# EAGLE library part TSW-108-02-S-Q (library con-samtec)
THROUGH-HOLE .025" SQ POST HEADER Source: Samtec TSW.pdf
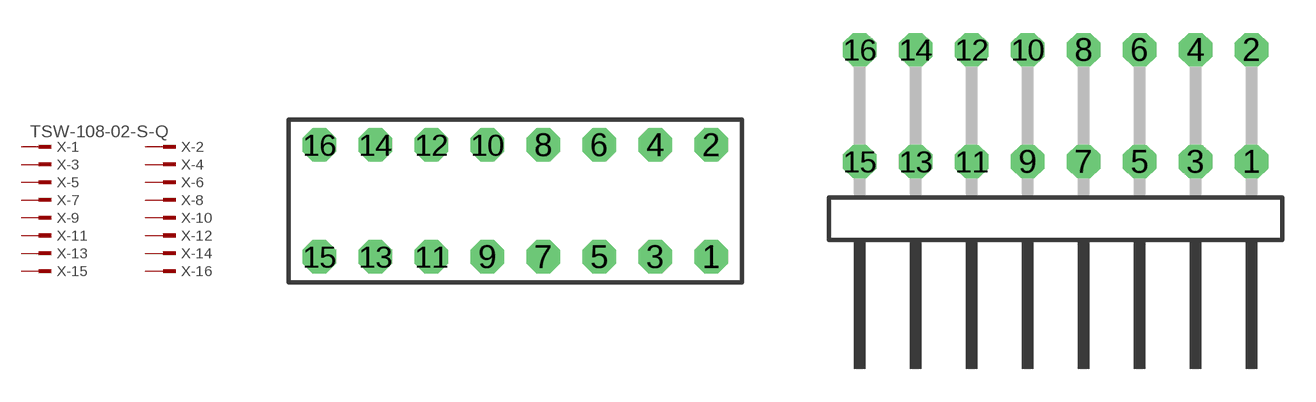
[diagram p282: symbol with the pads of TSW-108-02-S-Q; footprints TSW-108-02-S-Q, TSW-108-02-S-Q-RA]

Designator prefix X; gates -1=MPINV -2=MPIN -3=MPIN -4=MPIN -5=MPIN -6=MPIN -7=MPIN -8=MPIN -9=MPIN -10=MPIN -11=MPIN -12=MPIN -13=MPIN -14=MPIN -15=MPIN -16=MPIN

## TSW-108-02-S-Q (OC_FARNELL: unknown; OC_NEWARK: unknown)  [TSW-108-02-S-Q]
1  -1:1  pas
2  -2:1  pas
3  -3:1  pas
4  -4:1  pas
5  -5:1  pas
6  -6:1  pas
7  -7:1  pas
8  -8:1  pas
9  -9:1  pas
10  -10:1  pas
11  -11:1  pas
12  -12:1  pas
13  -13:1  pas
14  -14:1  pas
15  -15:1  pas
16  -16:1  pas

## TSW-108-02-S-Q-RA (OC_FARNELL: unknown; OC_NEWARK: unknown)  [TSW-108-02-S-Q-RA]
Pads as for TSW-108-02-S-Q

## Footprint TSW-108-02-S-Q (pad centres in mm)
THROUGH-HOLE .025" SQ POST HEADER Source: Samtec TSW.pdf
drill 1 pad 1.5 octagon: 1 8.89,-2.54; 2 8.89,2.54; 3 6.35,-2.54; 4 6.35,2.54; 5 3.81,-2.54; 6 3.81,2.54; 7 1.27,-2.54; 8 1.27,2.54; 9 -1.27,-2.54; 10 -1.27,2.54; 11 -3.81,-2.54; 12 -3.81,2.54; 13 -6.35,-2.54; 14 -6.35,2.54; 15 -8.89,-2.54; 16 -8.89,2.54

## Footprint TSW-108-02-S-Q-RA (pad centres in mm)
THROUGH-HOLE .025" SQ POST HEADER Source: Samtec TSW.pdf
drill 1 pad 1.5 octagon: 1 8.89,1.524; 2 8.89,6.604; 3 6.35,1.524; 4 6.35,6.604; 5 3.81,1.524; 6 3.81,6.604; 7 1.27,1.524; 8 1.27,6.604; 9 -1.27,1.524; 10 -1.27,6.604; 11 -3.81,1.524; 12 -3.81,6.604; 13 -6.35,1.524; 14 -6.35,6.604; 15 -8.89,1.524; 16 -8.89,6.604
